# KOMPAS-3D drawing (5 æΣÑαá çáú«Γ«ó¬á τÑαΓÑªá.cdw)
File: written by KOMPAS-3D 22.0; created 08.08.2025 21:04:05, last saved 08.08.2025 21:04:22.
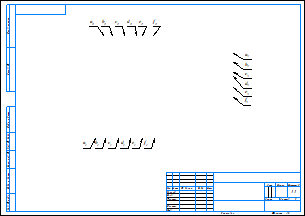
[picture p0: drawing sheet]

Sheet 1: A3, landscape

Document properties: Автор: user; Полное имя файла: G:\08 08 пятница\2025 НГ Лаб работы\Лаб 5 Сечения сферы и тора\5 Чертежи\Сфера Заготовка чертежа.cdw

Title block, sheet 1: scale: 1:1; Количество листов документа: 1; Форматы листов документа: A3

Dimensions and other numbers on the sheet: 1:1; 1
